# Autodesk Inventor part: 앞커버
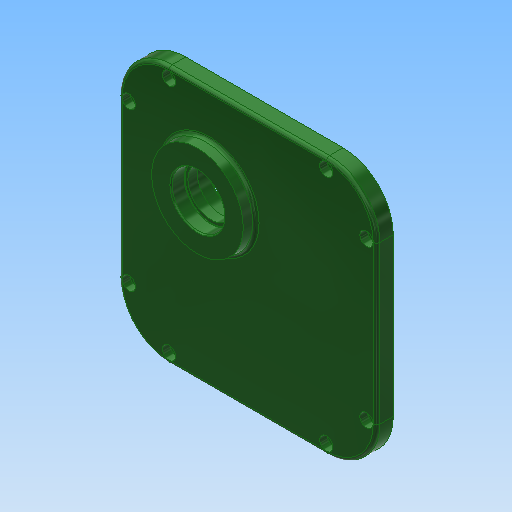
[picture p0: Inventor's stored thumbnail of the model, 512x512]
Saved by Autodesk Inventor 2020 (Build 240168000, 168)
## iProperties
Created: 2016-12
Part Number: 앞커버
Material: 알루미늄 6061
Document SubType Name: Modeling
Designer: mduedu
Density: 2.71 g/cm^3
Mass: 790.586 g
Surface Area: 580.683 cm^2
Volume: 291.729 cm^3
Appearance: 매끄러움 - 짙은 산림 녹색
Author: mduedu
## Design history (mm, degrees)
sketch "스케치1"
  geometry: L1 (-54, 50)-(-54, -44); L2 (-24, 80)-(70, 80); L3 (100, 50)-(100, -44); L4 (70, -74)-(-24, -74); A1 r 30 centre (-24, -44) between (-54, -44) and (-24, -74); A2 r 30 centre (70, 50) between (100, 50) and (70, 80); A3 r 30 centre (70, -44) between (70, -74) and (100, -44); A4 r 30 centre (-24, 50) between (-24, 80) and (-54, 50); 1 further point
  constraints: 8 end point, 8 point on circle, 8 tangent, 4 centre point, 3 equal radius, 3 perpendicular, 1 horizontal
  dimensions: "d89" = 30 radius of A2; "d90" = 100 distance from line of L3 point (0, 0); "d91" = 154 distance between parallel lines of L4 L2; "d92" = 80 distance from line of point (0, 0) L2
extrude "돌출1" new body sketch "스케치1" distance "d3" = 14; taper "d4" = 0 deg
sketch "스케치2"
  geometry: C1 r 21 at (0, 26); 1 further point
  constraints: 1 centre point, 1 vertical alignment
  dimensions: "d5" = 42 diameter of C1; "d7" = 26 distance of C1.centre point (0, 0)
extrude "돌출2" join sketch "스케치2" distance "d8" = 3; taper "d9" = 0 deg
sketch "스케치3"
  geometry: C1 r 15 at (0, -28.87); C2 r 21 at (0, 26) reference; C3 r 15 at (-54.87, 26); 1 further point
  constraints: 2 centre point, 1 horizontal alignment, 1 vertical alignment
  dimensions: "d10" = 30 diameter of C1; "d71" = 54.87 distance of C1.centre C2.centre; "d94" = 30 diameter of C3; "d95" = 54.87 distance of C2.centre C3.centre
extrude "돌출3" join sketch "스케치3" distance "d12" = 3; taper "d13" = 0 deg
sketch "스케치4"
  geometry: C1 r 21 at (0, 26) reference; C2 r 28 at (0, 26); 1 further point
  constraints: 1 centre point, 1 coincident
  dimensions: "d14" = 56 diameter of C2
extrude "돌출4" join sketch "스케치4" distance "d15" = 7; taper "d16" = -5 deg
hole "구멍1" diameter "d19" = 35; stored, may be unused: countersink angle "d23" = 90 deg, drill point angle "d25" = 0 deg; dims "d17" = 10, "d18" = 10, "d20" = 6, "d21" = 4, "d22" = 2, "d24" = 10
hole "구멍2" diameter "d28" = 22; stored, may be unused: countersink angle "d32" = 90 deg, drill point angle "d34" = 0 deg; dims "d26" = 10, "d27" = 10, "d29" = 6, "d30" = 4, "d31" = 2, "d33" = 7
hole "구멍8" diameter "d98" = 22; stored, may be unused: countersink angle "d102" = 90 deg, drill point angle "d104" = 0 deg; dims "d96" = 10, "d97" = 10, "d99" = 6, "d100" = 4, "d101" = 2, "d103" = 7
hole "구멍3" diameter "d37" = 19; stored, may be unused: countersink angle "d41" = 90 deg, drill point angle "d43" = 0 deg; dims "d38" = 6, "d39" = 4, "d40" = 2, "d42" = 3, "d127" = 10, "d128" = 10
hole "구멍9" diameter "d107" = 19; stored, may be unused: countersink angle "d111" = 90 deg, drill point angle "d113" = 0 deg; dims "d108" = 6, "d109" = 4, "d110" = 2, "d112" = 3, "d129" = 10, "d130" = 10
hole "구멍4" diameter "d46" = 32; stored, may be unused: countersink angle "d50" = 90 deg, drill point angle "d52" = 0 deg; dims "d47" = 6, "d48" = 4, "d49" = 2, "d51" = 8.3, "d121" = 10, "d122" = 10
hole "구멍5" diameter "d55" = 28; stored, may be unused: countersink angle "d59" = 90 deg, drill point angle "d61" = 0 deg; dims "d56" = 6, "d57" = 4, "d58" = 2, "d60" = 8, "d119" = 10, "d120" = 10
fillet "모깎기1" dims "d62" = 0.3
fillet "모깎기2" dims "d63" = 2
chamfer "모따기1" distance "d64" = 1; stored, may be unused: second distance "d65" = 2, angle "d66" = 45 deg
fillet "모깎기4" dims "d68" = 2
fillet "모깎기6" dims "d70" = 2
sketch "스케치5"
  geometry: L1 (70, 80)-(-24, 80) reference; L2 (100, -44)-(100, 50) reference; L3 (-24, -74)-(70, -74) reference; L4 (-54, 50)-(-54, -44) reference; L5 (-48, 50)-(-48, -44); L6 (-24, -68)-(70, -68); L7 (94, -44)-(94, 50); L8 (70, 74)-(-24, 74); A1 r 30 centre (70, 50) between (100, 50) and (70, 80) reference; A2 r 30 centre (70, -44) between (70, -74) and (100, -44) reference; A3 r 30 centre (-24, -44) between (-54, -44) and (-24, -74) reference; A4 r 30 centre (-24, 50) between (-24, 80) and (-54, 50) reference; A5 r 24 centre (-24, -44) between (-48, -44) and (-24, -68); A6 r 24 centre (70, -44) between (70, -68) and (94, -44); A7 r 24 centre (70, 50) between (94, 50) and (70, 74); A8 r 24 centre (-24, 50) between (-24, 74) and (-48, 50)
  constraints: 8 end point, 8 point on circle, 4 centre point, 7 other
  dimensions: "d93" = 6 distance between parallel lines of L5 L4
sketch "스케치7"
  geometry: L1 (70, 74)-(-24, 74) reference; L2 (94, -44)-(94, 50) reference; L3 (-24, -68)-(70, -68) reference; L4 (-48, 50)-(-48, -44) reference; A1 r 24 centre (70, 50) between (94, 50) and (70, 74) reference; A2 r 24 centre (70, -44) between (70, -68) and (94, -44) reference; A3 r 24 centre (-24, -44) between (-48, -44) and (-24, -68) reference; A4 r 24 centre (-24, 50) between (-24, 74) and (-48, 50) reference; 8 further points
  constraints: 8 coincident
hole "구멍7" sketch "스케치7" at (-48, 50), (-48, -44), (-24, -68), (70, -68), (94, -44), (94, 50), (70, 74), (-24, 74) diameter "d80" = 4.5; stored, may be unused: countersink angle "d84" = 90 deg, drill point angle "d86" = 0 deg; dims "d81" = 6, "d82" = 8, "d83" = 4.6, "d85" = 8
sketch "스케치8"
  geometry: L1 (-70, 80)-(24, 80) reference; L2 (-100, -44)-(-100, 50) reference; L3 (24, -74)-(-70, -74) reference; L4 (54, 50)-(54, -44) reference; L5 (42, -44)-(42, 50); L6 (24, 68)-(-70, 68); L7 (-88, 50)-(-88, -44); L8 (-70, -62)-(24, -62); A1 r 30 centre (-70, 50) between (-70, 80) and (-100, 50) reference; A2 r 30 centre (-70, -44) between (-100, -44) and (-70, -74) reference; A3 r 30 centre (24, 50) between (54, 50) and (24, 80) reference; A4 r 30 centre (24, -44) between (24, -74) and (54, -44) reference; A5 r 18 centre (24, 50) between (42, 50) and (24, 68); A6 r 18 centre (-70, 50) between (-70, 68) and (-88, 50); A7 r 18 centre (-70, -44) between (-88, -44) and (-70, -62); A8 r 18 centre (24, -44) between (24, -62) and (42, -44); 1 further point
  constraints: 8 end point, 8 point on circle, 4 centre point, 7 other
  dimensions: "d116" = 12 distance between parallel lines of L5 L4
extrude "돌출5" cut sketch "스케치8" distance "d117" = 4; taper "d118" = 0 deg
chamfer "모따기2" distance "d123" = 0.8; stored, may be unused: second distance "d124" = 2, angle "d125" = 30 deg
fillet "모깎기7" dims "d126" = 0.5
node "솔리드1"
